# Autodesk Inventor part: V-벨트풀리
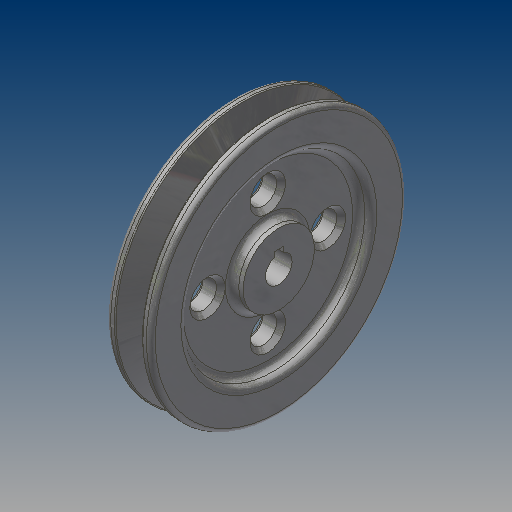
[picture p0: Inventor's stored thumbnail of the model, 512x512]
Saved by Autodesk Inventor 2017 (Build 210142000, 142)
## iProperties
Created: 2015-09
Part Number: V-벨트풀리
Material: 강철, 연강
Document SubType Name: Modeling
Designer: mduedu
Density: 1 g/cm^3
Appearance: 강철
Author: mduedu
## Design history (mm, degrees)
sketch "스케치1"
  geometry: L1 (-10, 0)-(10, 0); L2 (-10, 0)-(-10, 57.5); L3 (-10, 57.5)-(-6.062, 57.5); L4 (-6.062, 57.5)-(-2.001, 45); L5 (-2.001, 45)-(2.001, 45); L6 (2.001, 45)-(6.062, 57.5); L7 (6.062, 57.5)-(10, 57.5); L8 (10, 57.5)-(10, 0); L9 (0, 0)-(0, 45); L10 (-10, 53)-(10, 53); 3 further points
  constraints: 20 end point, 6 point on line, 3 perpendicular, 2 midpoint, 2 parallel, 2 symmetric about line, 1 coincident, 1 collinear, 1 equal length, 1 horizontal, 1 vertical, 1 vertical alignment
  dimensions: "d0" = 20 distance between parallel lines of L8 L2; "d2" = 115 diameter of L3 L1; "d5" = 8 distance between parallel lines of L5 L10; "d6" = 9.2 distance of point (4.6, 53) point (-4.6, 53); "d7" = 36 deg angle of L6 L4; "d40" = 4.5 distance between parallel lines of L10 L3
revolve "회전1" sketch "스케치1" stored, may be unused: angle "d8" = 90 deg
sketch "스케치2"
  geometry: C1 r 16 at (0, 0); C2 r 41 at (0, 0); 1 further point
  constraints: 2 centre point, 2 coincident
  dimensions: "d9" = 32 diameter of C1; "d41" = 82 diameter of C2
extrude "돌출5" cut sketch "스케치2" distance "d42" = 5; taper "d43" = 0 deg
hole "구멍2" diameter "d46" = 12; stored, may be unused: countersink angle "d50" = 90 deg, drill point angle "d52" = 118 deg; dims "d44" = 10, "d45" = 10, "d47" = 6, "d48" = 4, "d49" = 2, "d51" = 8
sketch "스케치8"
  geometry: L1 (-2, 5.657)-(2, 5.657); L2 (2, 5.657)-(2, 7.8); L3 (2, 7.8)-(-2, 7.8); L4 (-2, 7.8)-(-2, 5.657); A1 r 6 centre (0, 0) between (-2, 5.657) and (2, 5.657) reference; 1 further point
  constraints: 8 end point, 2 parallel, 2 point on circle, 1 horizontal, 1 perpendicular
  dimensions: "d53" = 4 distance of L2.end L3.end; "d55" = 13.8 dimension on A1 L3
extrude "돌출6" cut sketch "스케치8" stored distance "d56" = 5; taper "d57" = 0 deg
sketch "스케치9"
  geometry: C1 r 6 at (0, 27); 1 further point
  constraints: 1 centre point, 1 vertical alignment
  dimensions: "d61" = 12 diameter of C1; "d62" = 27 distance of C1.centre point (0, 0)
extrude "돌출7" cut sketch "스케치9" stored distance "d63" = 5; taper "d64" = 0 deg
chamfer "모따기3" distance "d65" = 2; stored, may be unused: second distance "d66" = 2, angle "d67" = 45 deg
fillet "모깎기5" dims "d71" = 2, "d72" = 1, "d73" = 0.5
fillet "모깎기6" dims "d74" = 3
fillet "모깎기7" dims "d75" = 3
fillet "모깎기8" dims "d76" = 3
sketch "스케치10"
  geometry: C1 r 47.5 at (0, 0); 1 further point
  constraints: 1 centre point, 1 coincident, 1 other
  dimensions: "d77" = 95 diameter of C1
extrude "돌출8" join sketch "스케치10" distance "d80" = 0.5; taper "d81" = 0 deg
node "솔리드1"
mirror "대칭2"
pattern_circular "원형 패턴1" dims "d69" = 360 deg
